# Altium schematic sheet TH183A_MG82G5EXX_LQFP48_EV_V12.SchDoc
size 289 x 199 mm; PageSetup: Record=PageOptions|CenterHorizontal=True|CenterVertical=True|PrintScale=1.01|XCorrection=1.00|YCorrection=1.00|PrintKind=0|BorderSize=5000000|LeftOffset=0|BottomOffset=0|Orientation=2|PaperLength=1000|PaperWidth=1000|Scale=100|PaperSource=7|PrintQuality=-4|MediaType=1|DitherType=10|PaperKind=A4|PrintScaleMode=1
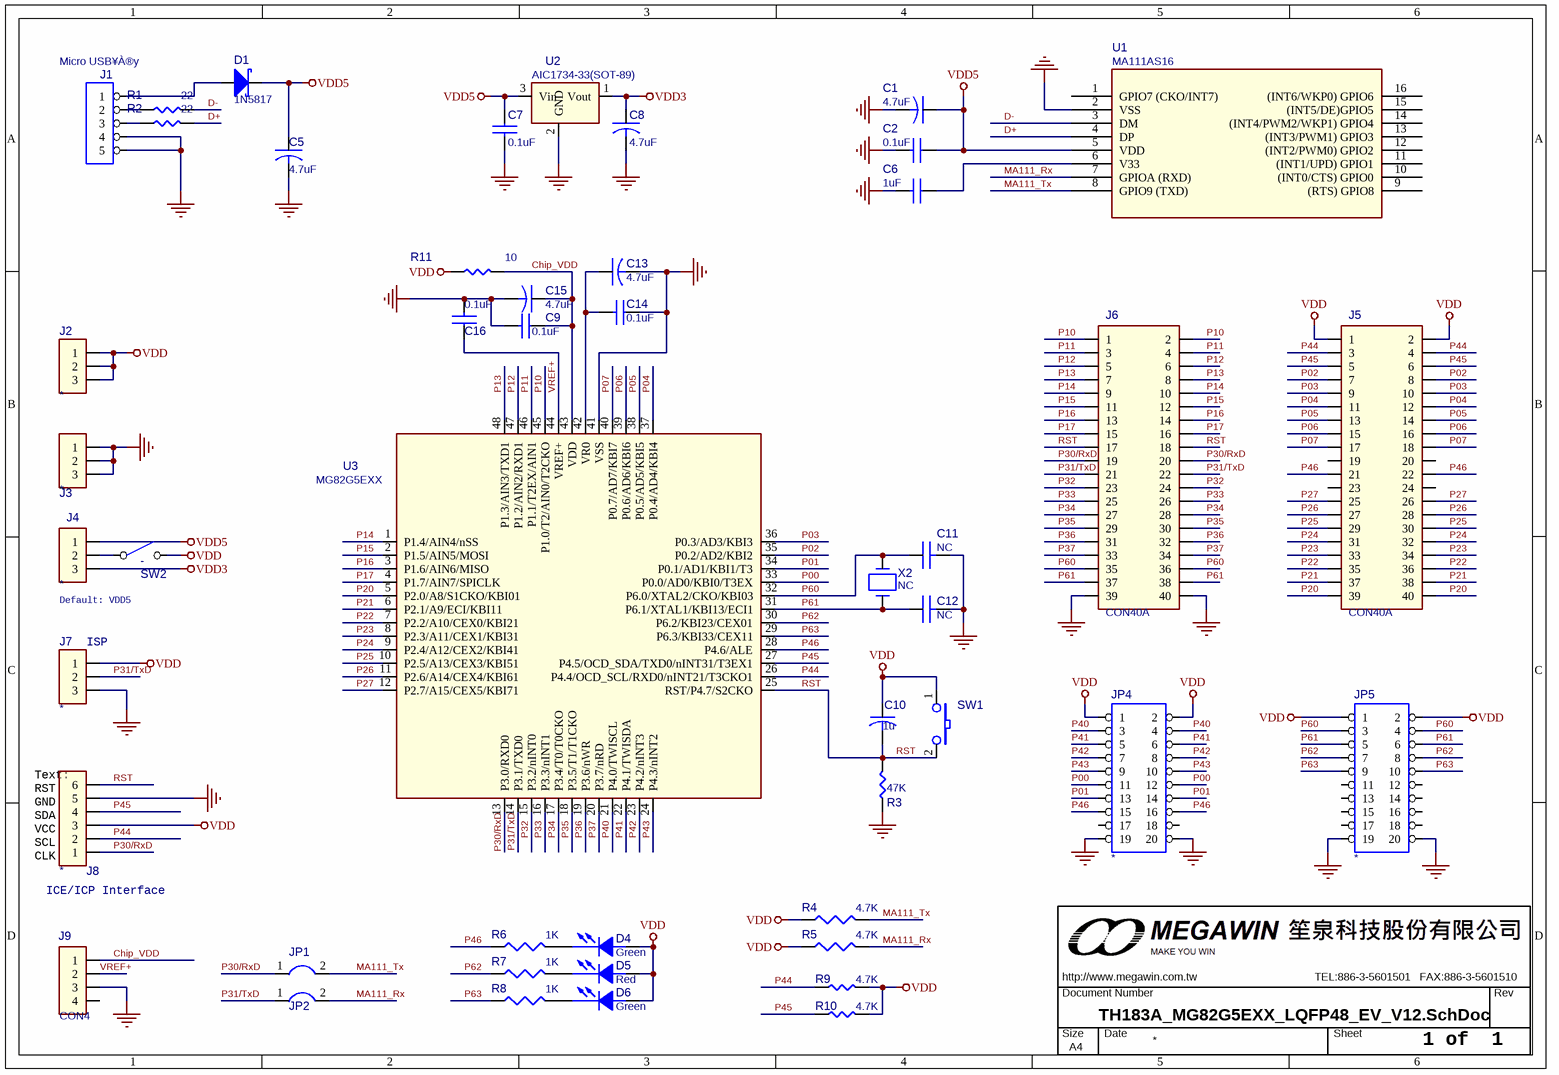
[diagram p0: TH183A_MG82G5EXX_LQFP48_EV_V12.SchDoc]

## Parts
C1  4.7uF  [0805C]
C2  0.1uF  [0805C]
C5  4.7uF  [1206C]
C6  1uF  [0805C]
C7  0.1uF  [0805C]
C8  4.7uF  [0805C]
C9  0.1uF  [0805C]
C10  1u  [0805C]
C11  NC  [0805C]
C12  NC  [0805C]
C13  4.7uF  [0805C]
C14  0.1uF  [0805C]
C15  4.7uF  [0805C]
C16  0.1uF  [0805C]
D1  1N5817  [D5817_SMD_1]
D4  Green  [0805D]
D5  Red  [0805D]
D6  Green  [0805D]
J1  Micro USB¥À®y  [JACK_USB_SMD290X220P065]
J2  *  [PS3P254]
J3  *  [PS3P254]
J4  *  [JUMP3_SMD]
J5  CON40A  [PS20X2P254]
J6  CON40A  [PS20X2P254]
J7  *  [PS3P254f_90]
J8  *  [PS6P254F_90]
J9  CON4  [PS4p254]
JP1  JUMPER2  [PS2P254]  (value not drawn)
JP2  JUMPER2  [PS2P254]  (value not drawn)
JP4  *  [PS10X2P254]
JP5  *  [PS10X2P254]
MW1  OrgAddr3: TEL:886-3-5601501   FAX:886-3-5601510  Page Size: A4  [MEGAWIN10_1]  (hidden comment: MW_A4_1)  (graphical)
R1  22  [0805R]
R2  22  [0805R]
R3  47K  [0805R]
R4  4.7K  [0805R]
R5  4.7K  [0805R]
R6  1K  [0805R]
R7  1K  [0805R]
R8  1K  [0805R]
R9  4.7K  [0805R]
R10  4.7K  [0805R]
R11  10  [0805R]
SW1  SW TACT-SPST  [SW_T_2P]  (value not drawn)
SW2  -  [DIP2_SW]
U1  MA111AS16  [SO16_150P127]
U2  AIC1734-33(SOT-89)  [SOT89]
U3  MG82G5EXX  [LQFP48_7X7_050]
X2  NC  [X49U]

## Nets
GND_POWER: C1.2 C2.2 C5.2 C6.2 C7.2 C8.2 C9.2 C11.2 C12.2 C13.2 C14.1 C15.2 C16.2 J1.4 J1.5 J3.1 J3.2 J3.3 J6.39 J6.40 J7.3 J8.5 J9.3 JP4.19 JP4.20 JP5.19 JP5.20 R3.1 U1.2(VSS) U2.2(GND) U3.41(VSS)
VDD: C10.1(POS) D4.1(ANODE) D5.1(ANODE) D6.1(ANODE) J2.1 J2.2 J2.3 J5.1 J5.2 J7.1 J8.3 JP4.1 JP4.2 JP5.1 JP5.2 R4.1 R5.1 R9.2 R10.2 R11.1 SW1.1 SW2.2(NO)
VDD3: C8.1 J4.3 U2.1(Vout)
VDD5: C1.1 C2.1 C5.1 C7.1 D1.2(K) J4.1 U1.5(VDD) U2.3(Vin)
Chip_VDD: C9.1 C15.1 J9.1 R11.2 U3.43(VDD)
D+: R2.2 U1.4(DP)
D-: R1.2 U1.3(DM)
MA111_Rx: JP2.2 R5.2 U1.7(GPIOA_(RXD))
MA111_Tx: JP1.2 R4.2 U1.8(GPIO9_(TXD))
P00: JP4.11 JP4.12 U3.33(P0.0/AD0/KBI0/T3EX)
P01: JP4.13 JP4.14 U3.34(P0.1/AD1/KBI1/T3)
P02: J5.7 J5.8 U3.35(P0.2/AD2/KBI2)
P03: J5.9 J5.10 U3.36(P0.3/AD3/KBI3)
P04: J5.11 J5.12 U3.37(P0.4/AD4/KBI4)
P05: J5.13 J5.14 U3.38(P0.5/AD5/KBI5)
P06: J5.15 J5.16 U3.39(P0.6/AD6/KBI6)
P07: J5.17 J5.18 U3.40(P0.7/AD7/KBI7)
P10: J6.1 J6.2 U3.45(P1.0/T2/AIN0/T2CKO)
P11: J6.3 J6.4 U3.46(P1.1/T2EX/AIN1)
P12: J6.5 J6.6 U3.47(P1.2/AIN2/RXD1)
P13: J6.7 J6.8 U3.48(P1.3/AIN3/TXD1)
P14: J6.9 J6.10 U3.1(P1.4/AIN4/nSS)
P15: J6.11 J6.12 U3.2(P1.5/AIN5/MOSI)
P16: J6.13 J6.14 U3.3(P1.6/AIN6/MISO)
P17: J6.15 J6.16 U3.4(P1.7/AIN7/SPICLK)
P20: J5.39 J5.40 U3.5(P2.0/A8/S1CKO/KBI01)
P21: J5.37 J5.38 U3.6(P2.1/A9/ECI/KBI11)
P22: J5.35 J5.36 U3.7(P2.2/A10/CEX0/KBI21)
P23: J5.33 J5.34 U3.8(P2.3/A11/CEX1/KBI31)
P24: J5.31 J5.32 U3.9(P2.4/A12/CEX2/KBI41)
P25: J5.29 J5.30 U3.10(P2.5/A13/CEX3/KBI51)
P26: J5.27 J5.28 U3.11(P2.6/A14/CEX4/KBI61)
P27: J5.25 J5.26 U3.12(P2.7/A15/CEX5/KBI71)
P30/RxD: J6.19 J6.20 J8.1 JP1.1 U3.13(P3.0/RXD0)
P31/TxD: J6.21 J6.22 J7.2 JP2.1 U3.14(P3.1/TXD0)
P32: J6.23 J6.24 U3.15(P3.2/nINT0)
P33: J6.25 J6.26 U3.16(P3.3/nINT1)
P34: J6.27 J6.28 U3.17(P3.4/T0/T0CKO)
P35: J6.29 J6.30 U3.18(P3.5/T1/T1CKO)
P36: J6.31 J6.32 U3.19(P3.6/nWR)
P37: J6.33 J6.34 U3.20(P3.7/nRD)
P40: JP4.3 JP4.4 U3.21(P4.0/TWISCL)
P41: JP4.5 JP4.6 U3.22(P4.1/TWISDA)
P42: JP4.7 JP4.8 U3.23(P4.2/nINT3)
P43: JP4.9 JP4.10 U3.24(P4.3/nINT2)
P44: J5.3 J5.4 J8.2 R9.1 U3.26(P4.4/OCD_SCL/RXD0/nINT21/T3CKO1)
P45: J5.5 J5.6 J8.4 R10.1 U3.27(P4.5/OCD_SDA/TXD0/nINT31/T3EX1)
P46: J5.21 J5.22 JP4.15 JP4.16 R6.1 U3.28(P4.6/ALE)
P60: C11.1 J6.35 J6.36 JP5.3 JP5.4 U3.32(P6.0/XTAL2/CKO/KBI03) X2.2
P61: C12.1 J6.37 J6.38 JP5.5 JP5.6 U3.31(P6.1/XTAL1/KBI13/ECI1) X2.1
P62: JP5.7 JP5.8 R7.1 U3.30(P6.2/KBI23/CEX01)
P63: JP5.9 JP5.10 R8.1 U3.29(P6.3/KBI33/CEX11)
RST: C10.2(NEG) J6.17 J6.18 J8.6 R3.2 SW1.2 U3.25(RST/P4.7/S2CKO)
VREF+: C16.1 J9.2 U3.44(VREF+)
NetC6_1: C6.1 U1.6(V33)
NetC13_1: C13.1 C14.2 U3.42(VR0)
NetD1_1: D1.1(A) J1.1
NetD4_2: D4.2(CATHODE) R6.2
NetD5_2: D5.2(CATHODE) R7.2
NetD6_2: D6.2(CATHODE) R8.2
NetJ1_2: J1.2 R1.1
NetJ1_3: J1.3 R2.1
NetJ4_2: J4.2 SW2.1(COMMON)

Not connected (* = marked no-connect by the designer): J5 19 20 23 24; J9 4; JP4 17 18; JP5 11 12 13 14 15 16 17 18; U1 1(GPIO7_(CKO/INT7)) 9((RTS)_GPIO8) 10((INT0/CTS)_GPIO0) 11((INT1/UPD)_GPIO1) 12((INT2/PWM0)_GPIO2) 13((INT3/PWM1)_GPIO3) 14((INT4/PWM2/WKP1)_GPIO4) 15((INT5/DE)GPIO5) 16((INT6/WKP0)_GPIO6)

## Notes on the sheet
- Default: VDD5
- (near J7) ISP
- (near J8) Text:
  RST
  GND
  SDA
  VCC
  SCL
  CLK
- (near J8) ICE/ICP Interface
- 1 of  1

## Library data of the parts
C1 C5 C8 C13 C15 = CAP
C2 C6 C7 C9 C14 C16 = CAP NP
C10 = C
C11 C12 = C NP
D1 = DIODE_ZD: Schottky Diode
D4-D6 = LED
J1 = CON5: Connector
J2-J4 J7 = CON3
J8 = CON6
JP4 JP5 = CON10X2
R1-R3 R9-R11 = R
R4-R8 = R_Dup1
SW2 = SW-2
U2 = AIC1734-33(SOT-89)_0
U3 = MG82FG5C64_LQFP48
X2 = CRYSTAL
